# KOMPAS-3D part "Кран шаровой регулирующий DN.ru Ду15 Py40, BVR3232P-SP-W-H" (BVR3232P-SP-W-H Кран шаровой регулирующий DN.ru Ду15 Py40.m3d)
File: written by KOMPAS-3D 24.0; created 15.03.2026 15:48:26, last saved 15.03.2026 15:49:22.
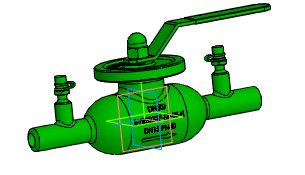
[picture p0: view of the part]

Document properties: Автор: Максим; Полное имя файла: D:\Rabota ebanaya\BVR3232P-SP-W-H Кран шаровой регулирующий Ду15-150\Типоразмеры\DN15\BVR3232P-SP-W-H Кран шаровой регулирующий DN.ru Ду15 Py40.m3d

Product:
- Body: Тело 1  | qty 1
    Масса: 2.546928
- Part/product: Кран шаровой регулирующий DN.ru Ду15 Py40  | designation BVR3232P-SP-W-H
    Масса: 1.5
    Раздел спецификации: Прочие изделия
    Примечание: D160-69406

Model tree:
1. Операция без истории:1

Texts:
  BVR3232P-SP-W-H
